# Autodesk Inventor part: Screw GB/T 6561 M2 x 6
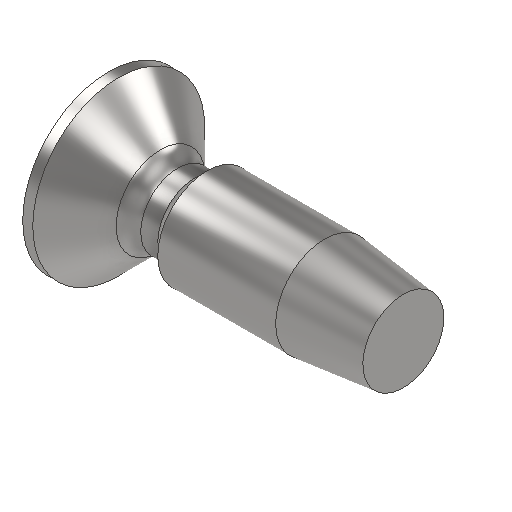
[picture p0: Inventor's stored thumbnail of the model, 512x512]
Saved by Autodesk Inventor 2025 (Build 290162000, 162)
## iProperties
Created: 2021-02
Part Number: Screw GB/T 6561 M2 x 6
Material: Acciaio, Dolce
Description: Cross recessed countersunk head thread forming screws
Document SubType Name: Modeling
Designer: Ryzen5700u
Density: 7.85 g/cm^3
Appearance: Default
Author: Ryzen5700u
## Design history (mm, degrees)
feature "Solid1"
node "Solido1"
